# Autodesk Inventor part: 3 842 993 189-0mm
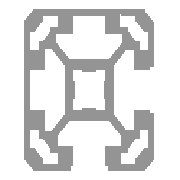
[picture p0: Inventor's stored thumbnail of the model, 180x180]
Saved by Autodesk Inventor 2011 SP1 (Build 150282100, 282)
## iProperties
Category: End -/-
Created: 2011-02
Part Number: 3 842 993 189-0mm
Document SubType Name: Modeling
Designer: SRW
Density: 2.71 g/cm^3
Categories: <MemberInstance><Categories><Category DisplayName="Structural Shapes" InternalName="089c4875-fa83-4c05-b084-43b9cc11f5ed" Mnemonic="GRDR"><CategoryParameter Dis
Stock Number: 3 842 993 189
Description: PROFILE 40x40 2SA, -/-
Material: Aluminum-6061
Mass: 40.3686 g
Surface Area: 148.351 cm^2
Volume: 14.8962 cm^3
G_L: 25.000 mm
Author: SRW
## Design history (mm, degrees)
node "Blocks"
  sketch "40X402SA"
    geometry: L1 (50.385, 10.18)-(50.385, 44.18); L2 (45.885, 17.68)-(45.885, 15.43); L3 (42.049, 37.43)-(37.885, 33.266); L4 (44.385, 37.43)-(42.049, 37.43); L5 (44.385, 32.18)-(44.385, 37.43); L6 (48.885, 32.18)-(44.385, 32.18); L7 (35.385, 41.18)-(35.385, 45.68); L8 (40.635, 41.18)-(35.385, 41.18); L9 (40.635, 38.844)-(40.635, 41.18); L10 (36.471, 34.68)-(40.635, 38.844); L11 (42.135, 42.68)-(42.135, 41.68); L12 (39.885, 42.68)-(42.135, 42.68); L13 (44.885, 38.93)-(45.885, 38.93); L14 (44.885, 45.68)-(39.885, 45.68); L15 (44.885, 44.43)-(44.885, 45.68); L16 (48.885, 41.68)-(47.635, 41.68); L17 (48.885, 36.68)-(48.885, 41.68); L18 (45.885, 38.93)-(45.885, 36.68); L19 (48.885, 22.18)-(48.885, 32.18); L20 (48.885, 12.68)-(48.885, 17.68); L21 (47.635, 12.68)-(48.885, 12.68); L22 (45.885, 15.43)-(44.885, 15.43); L23 (44.885, 8.68)-(44.885, 9.93); L24 (44.385, 22.18)-(48.885, 22.18); L25 (44.385, 16.93)-(44.385, 22.18); L26 (42.135, 12.68)-(42.135, 11.68); L27 (42.049, 16.93)-(44.385, 16.93); L28 (40.435, 15.716)-(40.435, 13.18); L29 (42.135, 11.68)-(39.885, 11.68); L30 (39.885, 8.68)-(44.885, 8.68); L31 (37.885, 33.266)-(37.885, 21.094); L32 (37.885, 21.094)-(42.049, 16.93); L33 (36.471, 19.68)-(40.435, 15.716); L34 (36.185, 8.68)-(36.185, 7.18); L35 (40.435, 13.18)-(35.385, 13.18); L36 (35.385, 13.18)-(35.385, 8.68); L37 (35.385, 8.68)-(36.185, 8.68); L38 (36.185, 7.18)-(47.385, 7.18); L39 (20.335, 15.716)-(24.299, 19.68); L40 (20.335, 13.18)-(20.335, 15.716); L41 (25.385, 13.18)-(20.335, 13.18); L42 (25.385, 8.68)-(25.385, 13.18); L43 (24.585, 8.68)-(25.385, 8.68); L44 (24.585, 7.18)-(24.585, 8.68); L45 (13.385, 7.18)-(24.585, 7.18); L46 (10.385, 21.38)-(10.385, 10.18); L47 (14.885, 15.43)-(14.885, 17.68); L48 (15.885, 15.43)-(14.885, 15.43); L49 (11.885, 17.68)-(11.885, 12.68); L50 (11.885, 12.68)-(13.135, 12.68); L51 (18.635, 11.68)-(18.635, 12.68); L52 (15.885, 9.93)-(15.885, 8.68); L53 (15.885, 8.68)-(20.885, 8.68); L54 (20.885, 11.68)-(18.635, 11.68); L55 (24.299, 19.68)-(36.471, 19.68); L56 (11.885, 21.38)-(10.385, 21.38); L57 (11.885, 22.18)-(11.885, 21.38); L58 (16.385, 22.18)-(11.885, 22.18); L59 (16.385, 17.13)-(16.385, 22.18); L60 (18.921, 17.13)-(16.385, 17.13); L61 (22.885, 21.094)-(18.921, 17.13); L62 (22.885, 33.266)-(22.885, 21.094); L63 (11.885, 32.18)-(16.385, 32.18); L64 (11.885, 32.98)-(11.885, 32.18)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; A1 r 3 centre (47.385, 44.18) between (50.385, 44.18) and (47.385, 47.18); A2 r 1.5 centre (39.885, 44.18) between (39.885, 45.68) and (39.885, 42.68); A3 r 1.5 centre (47.385, 36.68) between (45.885, 36.68) and (48.885, 36.68); A4 r 2.75 centre (44.885, 41.68) between (42.135, 41.68) and (44.885, 38.93); A5 r 2.75 centre (44.885, 41.68) between (47.635, 41.68) and (44.885, 44.43); A6 r 1.5 centre (47.385, 17.68) between (48.885, 17.68) and (45.885, 17.68); A7 r 3 centre (47.385, 10.18) between (47.385, 7.18) and (50.385, 10.18); A8 r 2.75 centre (44.885, 12.68) between (44.885, 9.93) and (47.635, 12.68); A9 r 2.75 centre (44.885, 12.68) between (44.885, 15.43) and (42.135, 12.68); A10 r 1.5 centre (39.885, 10.18) between (39.885, 11.68) and (39.885, 8.68); A11 r 3 centre (13.385, 10.18) between (10.385, 10.18) and (13.385, 7.18); A12 r 2.75 centre (15.885, 12.68) between (18.635, 12.68) and (15.885, 15.43); A13 r 2.75 centre (15.885, 12.68) between (13.135, 12.68) and (15.885, 9.93); A14 r 1.5 centre (20.885, 10.18) between (20.885, 8.68) and (20.885, 11.68); A15 r 5 centre (30.385, 27.18) between (34.971, 25.187) and (34.971, 29.173); A16 r 5 centre (30.385, 27.18) between (28.392, 22.594) and (32.378, 22.594); A17 r 1.5 centre (13.385, 17.68) between (14.885, 17.68) and (11.885, 17.68); A18 r 5 centre (30.385, 27.18) between (25.799, 29.173) and (25.799, 25.187); A19 r 5 centre (30.385, 27.18) between (32.378, 31.765) and (28.392, 31.765); A20 r 3 centre (13.385, 44.18) between (13.385, 47.18) and (10.385, 44.18); A21 r 1.5 centre (20.885, 44.18) between (20.885, 42.68) and (20.885, 45.68); A22 r 2.75 centre (15.885, 41.68) between (15.885, 44.43) and (13.135, 41.68); A23 r 2.75 centre (15.885, 41.68) between (15.885, 38.93) and (18.635, 41.68); A24 r 1.5 centre (13.385, 36.68) between (11.885, 36.68) and (14.885, 36.68); 1 further point
    constraints: 200 end point, 48 point on circle, 24 centre point, 1 coincident
node "Start Plane"
node "End Plane"
sketch "Sketch1"
  geometry: 1 further point
  constraints: 1 other
extrude "Body" new body sketch "Sketch1" stored distance "d4" = 0.13; taper "d5" = 0 deg
node "Driven Length"
  sketch "Sketch51"
    geometry: L1 (0, 0)-(10, 0) reference
    constraints: 2 end point, 1 horizontal
  workplane "Work Plane22"
  sketch "Sketch52"
    geometry: L1 (-28, 0)-(28, 0) reference; L2 (-28, 25)-(28, 25) reference
    dimensions: "d7" = 25 distance between parallel lines of L1 L2 (derived)
sketch "Sketch9"
  geometry: 1 further point
hole "M12/-" sketch "Sketch9" at (0, 0) diameter "d17" = 10.106; stored, may be unused: countersink angle "d21" = 90 deg, drill point angle "d23" = 118 deg; dims "d18" = 6, "d19" = 4, "d20" = 2, "d22" = 55
sketch "Sketch10"
  geometry: 1 further point
hole "-/M12" sketch "Sketch10" at (0, 0) diameter "d24" = 10.106; stored, may be unused: countersink angle "d28" = 90 deg, drill point angle "d30" = 118 deg; dims "d25" = 6, "d26" = 4, "d27" = 2, "d29" = 55
sketch "Sketch11"
  geometry: L1 (-13.7, 0)-(12.2, 0) reference; C1 r 8.5 at (0, 20); 1 further point
  constraints: 1 centre point, 1 vertical alignment
  dimensions: "d31" = 20 distance from line of C1.centre L1; "d32" = 17 diameter of C1
extrude "D17/-" cut sketch "Sketch11" stored distance "d33" = 10; taper "d34" = 0 deg
sketch "Sketch12"
  geometry: L1 (-13.7, 25)-(12.2, 25) reference; C1 r 8.5 at (0, 5); 1 further point
  constraints: 1 centre point, 1 vertical alignment
  dimensions: "d35" = 17 diameter of C1; "d36" = 20 distance from line of L1 C1.centre
extrude "-/D17" cut sketch "Sketch12" stored distance "d37" = 10; taper "d38" = 0 deg
sketch "Sketch13"
  geometry: L1 (-12.98, 0)-(7.88, 0) reference; C1 r 4.9 at (0, 20); 1 further point
  constraints: 1 centre point, 1 vertical alignment
  dimensions: "d39" = 9.8 diameter of C1; "d40" = 20 distance from line of C1.centre L1
extrude "D9.8/-" cut sketch "Sketch13" stored distance "d41" = 10; taper "d42" = 0 deg
sketch "Sketch14"
  geometry: L1 (-12.98, 25)-(7.88, 25) reference; C1 r 4.9 at (0, 5); 1 further point
  constraints: 1 centre point, 1 vertical alignment
  dimensions: "d43" = 9.8 diameter of C1; "d44" = 20 distance from line of L1 C1.centre
extrude "-/D9.8" cut sketch "Sketch14" stored distance "d45" = 10; taper "d46" = 0 deg
sketch "Sketch15"
  geometry: L1 (-6.86, 25)-(6.86, 25) reference; C1 r 4.9 at (0, 5); 1 further point
  constraints: 1 centre point, 1 vertical alignment
  dimensions: "d47" = 9.8 diameter of C1; "d48" = 20 distance from line of L1 C1.centre
extrude "-/D9.8VS" cut sketch "Sketch15" stored distance "d49" = 10; taper "d50" = 0 deg
sketch "Sketch26"
  geometry: L1 (-6.86, 0)-(6.86, 0) reference; C1 r 4.9 at (0, 20); 1 further point
  constraints: 1 centre point, 1 vertical alignment
  dimensions: "d62" = 9.8 diameter of C1; "d65" = 20 distance from line of L1 C1.centre
extrude "D9.8VS/-" cut sketch "Sketch26" stored distance "d63" = 10; taper "d64" = 0 deg
sketch "Sketch37"
  geometry: L1 (-11.9, 0)-(11.9, 0) reference; L2 (-11.9, 25)-(11.9, 25) reference; C1 r 8.5 at (0, 20); 1 further point
  constraints: 1 centre point, 1 vertical alignment
  dimensions: "d76" = 20 distance from line of C1.centre L1; "d77" = 17 diameter of C1
extrude "D17VS/-" cut sketch "Sketch37" stored distance "d78" = 10; taper "d79" = 0 deg
sketch "Sketch38"
  geometry: L1 (-11.9, 25)-(11.9, 25) reference; C1 r 8.5 at (0, 5); 1 further point
  constraints: 1 centre point, 1 vertical alignment
  dimensions: "d80" = 17 diameter of C1; "d81" = 20 distance from line of L1 C1.centre
extrude "-/D17VS" cut sketch "Sketch38" stored distance "d82" = 10; taper "d83" = 0 deg
body "Solid1"
node "40X402SA:1"
other parameters: "Length" = 25, "G_OFFSET_START" = 0 [user parameter; used in 2 equation terms], "G_OFFSET_END" = 0 [user parameter; used in 2 equation terms], "d2" = 0 (computed from G_OFFSET_START), "d3" = 25 (= Length + G_OFFSET_END), "G_L" = 25 (= d7) [user parameter], "Length2" = 25 (= G_OFFSET_START + Length + G_OFFSET_END) [user parameter], "d96" = 90 deg
